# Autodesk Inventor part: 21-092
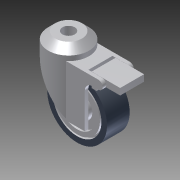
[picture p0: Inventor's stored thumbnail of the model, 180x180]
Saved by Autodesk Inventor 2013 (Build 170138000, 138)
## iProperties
Created: 2004-11
Part Number: 21-092
Document SubType Name: Modeling
Designer: Autodesk, Inc.
Manufacturer: Standard
Standards Organization: Custom
Description: CASTER, SWIVEL, WHEEL BRAKE
Catalog Web Link: http://www.parker.com/ead/cm1.asp?cmid=809
Vendor: PARKER IPS
Mass: 55.712 g
Surface Area: 207.15 cm^2
Volume: 55.712 cm^3
Density: 1 g/cm^3
Material: Allgemein
CAGE: 1LJX3
Dept. ID: Product Design
Description #2: ---
Finish #1: ---
Finish #2: ---
Material ID: ---
Project Number: ---
Description: Casters
Order Number: 21-092
Selection: Casters
Supplier: Parker Hannifin Corp., Industrial Profile Systems Div.
Author: Autodesk, Inc.
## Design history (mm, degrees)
feature "Base1"
sketch "Sketch1"
  geometry: C1 r 15.345 at (0, 0) reference; C2 r 19.05 at (0, 0); C3 r 20.32 at (0, 0)
  constraints: 2 centre point, 2 coincident
  dimensions: "d0" = 38.1 diameter of C2; "d1" = 1.27 radial gap between concentric circles of C2 C3
extrude "Extrusion1" cut sketch "Sketch1" distance "d2" = 2.54; taper "d3" = 0 deg
mirror "Mirror1"
node "Ground"
body "Solid1"
